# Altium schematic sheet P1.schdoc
size 297 x 209 mm; Symbol: Drawing-Symbol_A4; Company: 嘉立创EDA; Version: V1.0; Page Size: A4; @Project Name: 自行车流水尾灯（朵拉版）; @Page Count: 1; @Update Date: 2025-09-01; @Create Date: 2025-06-24; @Schematic Name: Schematic1; @Page No: 1; @Page Name: P1; @Create Time: 11:43:55; @Update Time: 18:54:02; Border: 1; Width: 1170; Height: 825; Region Start: 1; X Region Count: 6; Y Region Count: 4; Blade Width: 10; Title Block Position: 3; Title Block: 1; @Board Name: Board1; Device: Drawing-Symbol_A4
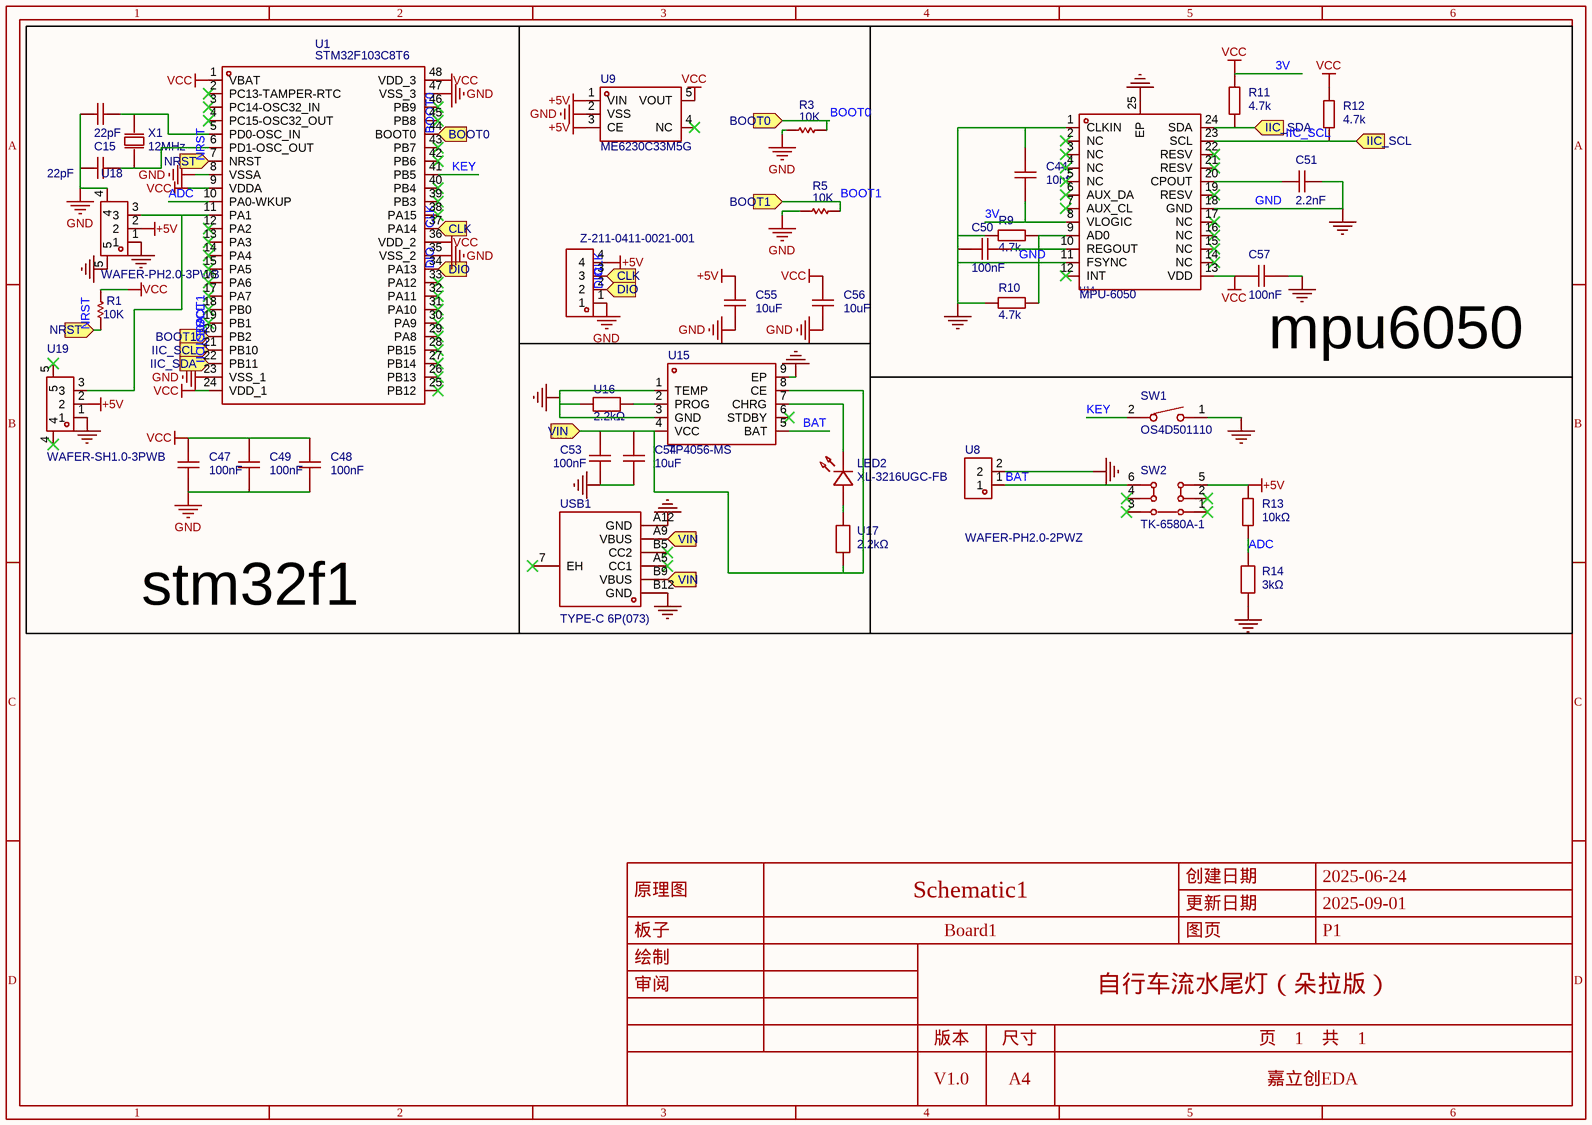
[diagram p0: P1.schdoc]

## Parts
C15  22pF  [C0805]
C16  22pF  [C0805]
C44  10nf  [C0805]
C47  100nF  [C0805]
C48  100nF  [C0805]
C49  100nF  [C0805]
C50  100nF  [C0805]
C51  2.2nF  [C0805]
C53  100nF  [C0805]
C54  10uF  [C0805]
C55  10uF  [C0805]
C56  10uF  [C0805]
C57  100nF  [C0805]
H3  Z-211-0411-0021-001  [HDR-TH_4P-P2.54-V-M]
LED2  XL-3216UGC-FB  [LED1206-FD_GREEN-EH]
R1  10K  [R0805]
R3  10K  [R0805]
R5  10K  [R0805]
R9  4.7k  [R0805_1]
R10  4.7k  [R0805_1]
R11  4.7k  [R0805_1]
R12  4.7k  [R0805_1]
R13  10kΩ  [R0805]
R14  3kΩ  [R0805]
SW1  OS4D501110  [SW-SMD_L6.0-W6.0-P6.00-LS6.8]
SW2  TK-6580A-1  [SW-TH_TK-6580A-1]
U1  STM32F103C8T6  [LQFP-48_L7.0-W7.0-P0.50-LS9.0-BL]
U8  WAFER-PH2.0-2PWZ  [CONN-TH_2P-P2.00_GP01-2001WR-2P]
U9  ME6230C33M5G  [TSOT-23-5_L2.9-W1.6-P0.95-LS2.8-BR]
U14  MPU-6050  [QFN-24_L4.0-W4.0-P0.50-BL-EP2.7]
U15  TP4056-MS  [SOP-8_L4.9-W3.9-P1.27-LS6.0-TL-EP]
U16  2.2kΩ  [R0805]
U17  2.2kΩ  [R0805]
U18  WAFER-PH2.0-3PWB  [CONN-SMD_3P-P2.00_XUNPU_WAFER-PH2.0-3PWB]
U19  WAFER-SH1.0-3PWB  [CONN-SMD_3P-P1.00_WAFER-SH1.0-3PWB]
USB1  TYPE-C 6P(073)  [TYPE-C-SMD_TYPE-C-6P-073]
X1  12MHz  [OSC-SMD_L5.0-W3.2]

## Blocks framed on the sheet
stm32f1: C15 C16 C47-C49 R1 U1 U18 U19 X1
mpu6050: C44 C50 C51 C57 R9-R12 U14

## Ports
BOOT0 (in), BOOT1 (in), CLK (in), DIO (in), IIC_SCL (in), IIC_SDA (in), NRST (in), VIN (in)

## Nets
3V: C44.1 C47.2 C48.2 C49.2 C56.2 C57.2 R1.2 R11.1 R12.1 U1.1(VBAT) U1.9(VDDA) U1.24(VDD_1) U1.36(VDD_2) U1.48(VDD_3) U9.5(VOUT) U14.8(VLOGIC) U14.13(VDD)  [also labelled VCC]
+5V: C55.2 H3.4 R13.2 SW2.5 U9.1(VIN) U9.3(CE) U18.2 U19.2
GND: C15.1 C16.1 C44.2 C47.1 C48.1 C49.1 C50.1 C51.2 C53.1 C54.1 C55.1 C56.1 C57.1 H3.1 R3.2 R5.2 R9.2 R10.2 R14.1 SW1.1 U1.8(VSSA) U1.23(VSS_1) U1.35(VSS_2) U1.47(VSS_3) U8.2 U9.2(VSS) U14.1(CLKIN) U14.11(FSYNC) U14.18(GND) U14.25(EP) U15.1(TEMP) U15.3(GND) U15.9(EP) U16.1 U18.1 U18.4 U18.5 U19.1 USB1.A12(GND) USB1.B12(GND)
ADC: R13.1 R14.2 U1.10(PA0-WKUP)
BAT: SW2.6 U8.1 U15.5(BAT)
BOOT0: R3.1 U1.44(BOOT0) ; port BOOT0
BOOT1: R5.1 U1.20(PB2) ; port BOOT1
CLK: H3.3 U1.37(PA14) ; port CLK
DIO: H3.2 U1.34(PA13) ; port DIO
IIC_SCL: R12.2 U1.21(PB10) U14.23(SCL) ; port IIC_SCL
IIC_SDA: R11.2 U1.22(PB11) U14.24(SDA) ; port IIC_SDA
KEY: SW1.2 U1.41(PB5)
NRST: R1.1 U1.7(NRST) ; port NRST
VIN: C53.2 C54.2 U15.4(VCC) U15.8(CE) U17.1 USB1.A9(VBUS) USB1.B9(VBUS) ; port VIN
NetC15_2: C15.2 U1.6(PD1-OSC_OUT) X1.1(OSC1)
NetC16_2: C16.2 U1.5(PD0-OSC_IN) X1.2(OSC2)
NetC50_2: C50.2 U14.10(REGOUT)
NetC51_1: C51.1 U14.20(CPOUT)
NetLED2_1: LED2.1(A) U17.2
NetLED2_2: LED2.2(K) U15.7(CHRG)
NetR9_1: R9.1 R10.1 U14.9(AD0)
NetU1_11: U1.11(PA1) U18.3 U19.3
NetU15_2: U15.2(PROG) U16.2

Not connected (* = marked no-connect by the designer): SW2 1* 2* 3* 4*; U1 2(PC13-TAMPER-RTC)* 3(PC14-OSC32_IN)* 4(PC15-OSC32_OUT)* 12(PA2)* 13(PA3)* 14(PA4)* 15(PA5)* 16(PA6)* 17(PA7)* 18(PB0)* 19(PB1)* 25(PB12)* 26(PB13)* 27(PB14)* 28(PB15)* 29(PA8)* 30(PA9)* 31(PA10)* 32(PA11)* 33(PA12)* 38(PA15)* 39(PB3)* 40(PB4)* 42(PB6)* 43(PB7)* 45(PB8)* 46(PB9)*; U9 4(NC)*; U14 2(NC)* 3(NC)* 4(NC)* 5(NC)* 6(AUX_DA)* 7(AUX_CL)* 12(INT)* 14(NC)* 15(NC)* 16(NC)* 17(NC)* 19(RESV)* 21(RESV)* 22(RESV)*; U15 6(STDBY)*; U19 4* 5*; USB1 7(EH)* A5(CC1)* B5(CC2)*

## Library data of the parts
C15 C16 = CL21C220JBANNNC: 容值:22pF;精度:±5%;额定电压:50V;材质(温度系数):C0G;; Manufacturer: SAMSUNG(三星); AddInBom: yes; ModelId: 1ba041120af144c991958decab20d241; ModelName: C0805_L2.0-W1.3-H1.3; ModelTransform: 78.74,51.181,0,0,0,0,0,0.0005,0; Tolerance: ±5%; Voltage Rated: 50V; Temperature Coefficient: C0G
C44 = CAP_0603: ConvertToPcb: yes; SymbolName: CapAcitance; ModelId: ac125912035d415993ca9572d50418b1; ModelName: C0603_L1.6-W0.8-H0.8; ModelTransform: 62.992,31.496,0,0,0,0,0,0,0
C47-C50 C53 C57 = CC0805KRX7R9BB104: 容值:100nF;精度:±10%;额定电压:50V;材质(温度系数):X7R;; Manufacturer: YAGEO(国巨); AddInBom: yes; ModelId: 1ba041120af144c991958decab20d241; ModelName: C0805_L2.0-W1.3-H1.3; ModelTransform: 78.74,51.181,0,0,0,0,0,0.0005,0; Tolerance: ±10%; Voltage Rated: 50V; Temperature Coefficient: X7R
C51 = CL21C222JBFNNNE: 容值:2.2nF;精度:±5%;额定电压:50V;材质(温度系数):C0G;; Manufacturer: SAMSUNG(三星); AddInBom: yes; ModelId: 1ba041120af144c991958decab20d241; ModelName: C0805_L2.0-W1.3-H1.3; ModelTransform: 78.74,51.181,0,0,0,0,0,0.0005,0; Tolerance: ±5%; Voltage Rated: 50V; Temperature Coefficient: C0G
C54-C56 = CGA0805X5R106K250MT: 容值:10uF;精度:±10%;额定电压:25V;温度系数:X5R;; Manufacturer: HRE(芯声); AddInBom: yes; ModelId: 1ba041120af144c991958decab20d241; ModelName: C0805_L2.0-W1.3-H1.3; ModelTransform: 78.74,51.181,0,0,0,0,0,0.0005,0; Tolerance: ±10%; Voltage Rating: 25V; Temperature Coefficient: X5R
H3 = Z-211-0411-0021-001: Manufacturer: Nextron(正凌); Manufacturer Part: Z-21104110021001; Convert to PCB: yes
LED2 = XL-3216UGC-FB: 发光颜色:翠绿色;正向电压(VF):-;功率:-;正向电流:-;主波长:-;透镜颜色:-;发光强度:-;发光角度:120°;载带方式:反贴;工作温度:-;; Manufacturer: XINGLIGHT(成兴光); AddInBom: yes; ModelId: 8b71279072344852848c1cea6905d4e5; ModelTransform: 125.984,62.99594,0,0,0,0,0,0,-20.8661; Emitted Color: 翠绿色; Viewing Angle: 120°; Mounting Sytle: 反贴
R1 R3 R5 = 10K: Origin Footprint: 0603R; value: 3k; Convert to PCB: yes
R9-R12 = Res_0603: Symbol: 电阻; ConvertToPcb: yes; ModelId: fc143cca1e79419f9cd78b61e9279f08; ModelName: R0603; ModelTransform: 31.8897,63.7794,0,90,0,0,0,0,0
R13 = 0805W8F1002T5E_C17414: 电阻类型:厚膜电阻;阻值:10kΩ;精度:±1%;功率:125mW;最大工作电压:150V;温度系数:±100ppm/℃;; Manufacturer: UNI-ROYAL(厚声); AddInBom: yes; ModelId: 37a81e68749a4138bd2dfa6897b24b85; ModelName: R0805_L2.0-W1.3-H0.6; ModelTransform: 78.74,51.181,0,0,0,0,0,-0.0005,0; Tolerance: ±1%; Power(Watts): 125mW; Overload Voltage (Max): 150V
R14 = FRC0805J302 TS: 电阻类型:厚膜电阻;阻值:3kΩ;精度:±5%;功率:125mW;最大工作电压:150V;温度系数:±100ppm/℃;; Manufacturer: FOJAN(富捷); AddInBom: yes; ModelId: 37a81e68749a4138bd2dfa6897b24b85; ModelName: R0805_L2.0-W1.3-H0.6; ModelTransform: 78.74,51.181,0,0,0,0,0,-0.0005,0; Tolerance: ±5%; Power(Watts): 125mW; Overload Voltage (Max): 150V
SW1 = OS4D501110: Manufacturer: SAMZO(三佐); AddInBom: yes; ModelId: 127e591f1f884657828a2cd0eb87bd97; ModelTransform: 269.56828,240.157,0,0,0,0,0,0,0
SW2 = TK-6580A-1: 电路结构:双刀双掷;自锁/无锁:自锁;安装方式:卧插;作用力:2.5N;机械寿命:-;; Manufacturer: Yuandi(元迪); AddInBom: yes; ModelId: fe3ea2f1a6e94ac78155457161d919fa; ModelTransform: 275.57378,407.47635,0,0,0,0,0,-130.039,-78.74; Circuit: 双刀双掷; Self Lock / No Lock: 自锁; Actuator Style: 方形柱塞; Actuator/Cap Color: 白色; Pin Style: PC引脚; Operating Force: 2.5N
U1 = STM32F103C8T6: Manufacturer: ST(意法半导体); Convert to PCB: yes
U8 = WAFER-PH2.0-2PWZ: 插针结构:1x2P;间距:2mm;安装方式:弯插;参考系列:PH;总PIN数:2P;排数:1;每排PIN数:2;行距:-;额定电流:2A;触头材质:黄铜;触头镀层:锡;工作温度:-25℃~+85℃;; Manufacturer: XUNPU(讯普); AddInBom: yes; ModelId: 2b14c02db7ac45e1979a75eee2c5a245; ModelTransform: 240.157,257.874,0,0,0,0,0,119.173,-137.795; Pins Structure: 1x2P; Pitch: 2mm; Reference Series: PH; Number of PINs Per Row: 2; Current Rating: 2A; Voltage Rating: 250V; Plastic Material: PA66; Flame Retardant Rating: UL94V-0; Z-Height of the Board: 4.7mm; X-Length of Bottom Edge on Board (Spacing Line): 6mm; Y-Width of Bottom Edge on Board: 6.05mm
U9 = ME6230C33M5G: 输出类型:固定;工作电压:5.5V;输出电压:3.3V;输出电流:400mA;电源纹波抑制比(PSRR):70dB@(1kHz);输出极性:正极;; Manufacturer: MICRONE(南京微盟); AddInBom: yes; ModelId: b5108020abe84f7bb0f3c398b43b6e0b; ModelName: TSOT-23-5_L2.9-W1.6-H1.00-LS2.8-P0.95; ModelTransform: 110.45568,114.173,0,180,0,0,0,0,0; Output Type: 固定; Voltage - Supply: 5.5V; Output Voltage: 3.3V; Output Current: 400mA; Output Configuration: 正极; Number of Outputs: 1
U14 = MPU-6050: 三轴加速度计和三轴陀螺仪，工作电压：2.375V~3.46V; Manufacturer: TDK InvenSense(应美盛); Symbol: MPU-6050_C24112; AddInBom: yes; ModelId: 36587cbfa4eb4c959e87e8b9fcde8e46; ModelName: QFN-24_L4.0-W4.0-H0.9-P0.50-; ModelTransform: 158.267,158.267,0,0,0,0,-0.01,0,0
U15 = TP4056-MS: 电源电压:4.2V~9V;最大充电电流:1A;电池类型:锂离子/聚合物;电池节数:1;; Manufacturer: MSKSEMI(美森科); AddInBom: yes; ModelId: 4f1f5228684a45afaa7af8cce46001de; ModelName: SOP-8_L4.9-W3.9-H1.45-LS6.0-P1.27; ModelTransform: 236.22,189.751,0,0,0,0,-0.051,0.515,0; Maximum Charge Current: 1A; Number of Cells: 1
U16 U17 = FRC0805J222 TS: 电阻类型:厚膜电阻;阻值:2.2kΩ;精度:±5%;功率:125mW;工作电压:150V;温度系数:±100ppm/℃;; Manufacturer: FOJAN(富捷); AddInBom: yes; ModelId: 37a81e68749a4138bd2dfa6897b24b85; ModelName: R0805_L2.0-W1.3-H0.6; ModelTransform: 78.74,51.181,0,0,0,0,0,-0.0005,0; Tolerance: ±5%; Power(Watts): 125mW; Voltage-Supply(Max): 150V
U18 = WAFER-PH2.0-3PWB: 插针结构:1x3P;间距:2mm;安装方式:卧贴;参考系列:PH;总PIN数:3P;排数:1;每排PIN数:3;行距:-;额定电流:2A;触头材质:黄铜;触头镀层:-;工作温度:-25℃~+85℃;; Manufacturer: XUNPU(讯普); AddInBom: yes; ModelId: 36d1fbe1ca854ac3a399e20600ab7918; ModelTransform: 393.7,334.645,0,180,0,0,0,-9.331,0; Pins Structure: 1x3P; Pitch: 2mm; Reference Series: PH; Number of PINs Per Row: 3; Current Rating: 2A; Voltage Rating: 250V; Plastic Material: LCP; Supplementary Features: 辅助焊脚; Z-Height of the Board: 5.6mm; X-Length of Bottom Edge on Board (Spacing Line): 10mm; Y-Width of Bottom Edge on Board: 8.5mm
U19 = WAFER-SH1.0-3PWB: 插针结构:1x3P;间距:1mm;安装方式:卧贴;参考系列:SH;总PIN数:3P;排数:1;每排PIN数:3;行距:-;额定电流:1A;触头材质:黄铜;触头镀层:-;工作温度:-25℃~+85℃;; Manufacturer: XUNPU(讯普); AddInBom: yes; ModelId: beca21b158df4599a6882f94b241bc84; ModelTransform: 211.0232,198.8185,0,0,0,0,-0.002,-17.404,0; Pins Structure: 1x3P; Pitch: 1mm; Reference Series: SH; Number of PINs Per Row: 3; Current Rating: 1A; Voltage Rating: 50V; Plastic Material: LCP; Supplementary Features: 辅助焊脚; Z-Height of the Board: 3.15mm; X-Length of Bottom Edge on Board (Spacing Line): 5.35mm; Y-Width of Bottom Edge on Board: 5.05mm
USB1 = TYPE-C 6P(073): 连接器类型:Type-C;标准:USB 3.1;公母:母;安装方式:卧贴;触点数量:6P;端口数量:1;额定电流 - 电源:3A;工作温度范围:-25℃~+85℃;; Manufacturer: SHOU HAN(首韩); AddInBom: yes; Gender: 母; Number of Ports: 1; Current Rating - Power (Max): 3A; Rated Voltage (Max): 5V; Connect-Disconnect Life: 1万次; Core Colour: 黑色; ModelId: 5572357f2a5242b0b12e4512f7b213ab; ModelTransform: 351.968,281.49546,0,0,0,0,0.002,-46.967,-39.37
X1 = X503212MSB2GI: 晶振类型:贴片晶振;频率:12MHz;常温频差:±10ppm;负载电容:20pF;频率稳定度:±20ppm;; Manufacturer: YXC(扬兴晶振); AddInBom: yes; ModelId: 36c8b961b9064b60a7c920ab5154e867; ModelName: OSC-SMD_L5.0-W3.2-H1.4; ModelTransform: 196.85,126.023,0,0,0,0,0,0,0; Normal temperature Frequency Tolerance: ±10ppm; Load Capacitance: 20pF; Frequency Stability: ±20ppm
